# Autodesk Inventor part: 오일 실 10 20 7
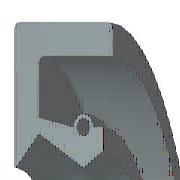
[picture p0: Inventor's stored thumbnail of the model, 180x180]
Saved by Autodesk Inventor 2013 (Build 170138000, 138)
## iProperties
IsCustomPart: 1
Created: 2012-02
Part Number: 오일 실 10 20 7
Material: 고무
Description: 오일-실
Document SubType Name: Modeling
Standard: KS B 2804
Designer: mduedu
Standards Organization: KS
Language: ko-KR
Size Designation: D - 10 20 7
Categories: <MemberInstance><Categories><Category DisplayName="샤프트 부품" InternalName="7f7aeb1f-a693-4053-b835-cee3144e0d98" Mnemonic="SHFT"><Category DisplayName="실링" Intern
Density: 0.93 g/cm^3
Author: mduedu
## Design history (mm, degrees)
revolve "본체" stored, may be unused: angle "d17" = 90 deg
revolve "스프링1" stored, may be unused: angle "d18" = 90 deg
body "Solid1"
sketch "스케치1"
  geometry: L1 (0, 10)-(7, 10); L2 (7, 8.25)-(1.75, 8.25); L3 (1.75, 6.75)-(4.9, 5); L4 (4.9, 5)-(0, 5); L5 (0, 0)-(9.586, 0) reference; L6 (4.9, 5)-(6.3, 5.875); L7 (0, 18)-(0, -3) reference; L8 (-1.941, 0)-(11.507, 0) reference; L9 (4.2, 7.1)-(1.75, 7.59); L10 (1.75, 7.59)-(1.75, 8.25); L11 (0, 10)-(0, 5.088); L12 (4.9, 5)-(0, 5); L13 (1.75, 6.75)-(0.152, 5.028); L14 (7, 10)-(7, 8.25); L15 (5.6, 7.1)-(6.3, 7.1); L16 (6.3, 7.1)-(6.3, 5.875); C1 r 0.455 at (4.9, 7.1); A1 r 0.7 centre (4.9, 7.1) between (5.6, 7.1) and (4.2, 7.1); A2 r 0.088 centre (0.088, 5.088) between (0, 5.088) and (0.152, 5.028); 1 further point
  constraints: 28 end point, 5 horizontal alignment, 5 point on line, 4 point on circle, 4 vertical alignment, 3 centre point, 3 tangent, 2 collinear, 2 horizontal, 2 perpendicular, 1 coincident, 1 parallel
  dimensions: "d0" = 20 diameter of L1 L5 (= SD2); "d1" = 1.75 distance of L1.end L2.start (= SD); "d2" = 0.91 diameter of C1 (= SPDI); "d3" = 1.4 diameter of A1 (= SPDA); "d4" = 10 diameter of L3.end L5 (= NND); "d5" = 13.5 diameter of L3.start L5 (= TKDM); "d7" = 15.18 diameter of L9.end L5 (= TKDM + 0.24 x SWDT); "d8" = 1.75 distance between parallel lines of L11 L10 (= SD); "d9" = 4.9 distance from line of L11 C1.centre (= SPDST); "d10" = 14.2 diameter of C1.centre L5 (= HLDM); "d11" = 0.0875 radius of A2 (= 0.25 x LAB); "d12" = 6.3 distance between parallel lines of L11 L16 (= SDI); "d13" = 11.75 diameter of L6.end L5 (= ABDM); "d14" = 7 distance from line of L11 L1.end (= SWDT)
fillet "모깎기1" dims "d6" = 0.3 (= RR)
other parameters: "SD2" = 20 [user parameter; used in 1 equation term], "SWDT" = 7 [user parameter; used in 2 equation terms], "RR" = 0.3 [user parameter; used in 1 equation term], "SD" = 1.75 [user parameter; used in 2 equation terms], "NND" = 10 [user parameter; used in 1 equation term], "SPDA" = 1.4 [user parameter; used in 1 equation term], "SPDI" = 0.91 [user parameter; used in 1 equation term], "TKDM" = 13.5 [user parameter; used in 2 equation terms], "HLDM" = 14.2 [user parameter; used in 1 equation term], "ABDM" = 11.75 [user parameter; used in 1 equation term], "SDI" = 6.3 [user parameter; used in 1 equation term], "SPDST" = 4.9 [user parameter; used in 1 equation term], "LAB" = 0.35 [user parameter; used in 1 equation term], "d15" = 0, "d16" = 0, "d19" = 0
